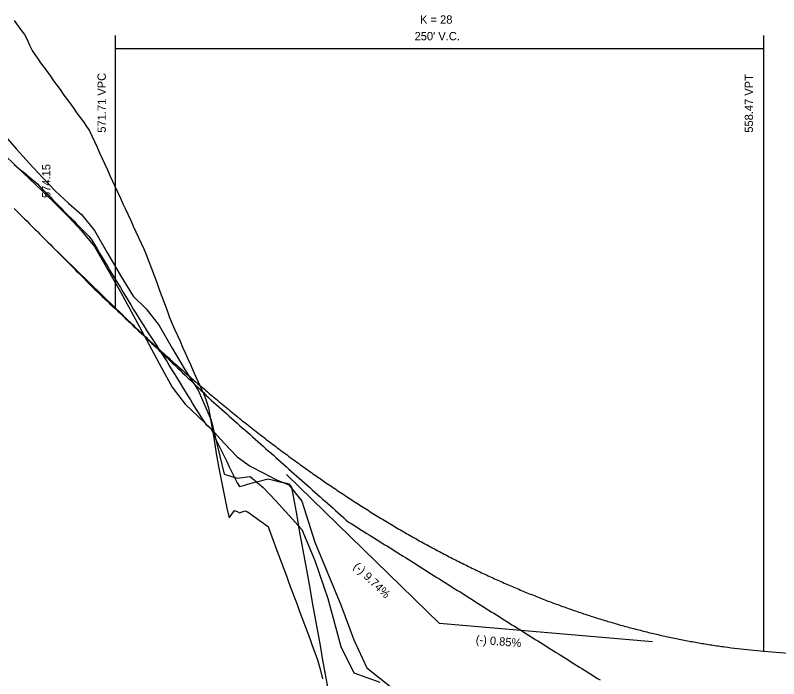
# Model space of a CAD drawing. Extents: x 1733571 to 1737171, y 1214895 to 1219895.
# Drawn here: x 1735066.5 to 1735360.8, y 1217969.6 to 1218225.5 of the extents above; entities that cross this region are included whole.
import ezdxf

# ---------------------------------------------------------------- set-up
doc = ezdxf.new("R2010")
doc.units = 0
for name, color, linetype in [('RD_DDB_GradeTX', 7, 'Continuous'), ('RD_DDB_Profile_EX', 7, 'Continuous'), ('RD_DDB_Profile_Lbl', 7, 'Continuous'), ('RD_DDB_Profile_PR', 7, 'Continuous'), ('RD_DDB_StripGrade', 7, 'Continuous'), ('RD_DDB_VCLbl', 7, 'Continuous'), ('RD_Sketch1', 7, 'Continuous'), ('RD_Sketch2', 7, 'Continuous'), ('RD_Sketch3', 7, 'Continuous'), ('RD_Sketch4', 7, 'Continuous')]:
    doc.layers.add(name, color=color, linetype=linetype)

msp = doc.modelspace()

# ---------------------------------------------------------------- linework, layer by layer
at = {"layer": 'RD_DDB_GradeTX'}
for p in [(1735170.98916, 1218048.35397), (1735312.11324, 1217983.88056)]:
    msp.add_line(p, (1735230.0087, 1217990.8522), dxfattribs=at)
at = {"layer": 'RD_DDB_Profile_EX'}
for points in [[(1735065.9887, 1218150.99954), (1735066.9887, 1218150.00594), (1735067.9887, 1218149.01167), (1735068.9887, 1218148.01672), (1735069.9887, 1218147.0211), (1735070.9887, 1218146.02371), (1735071.9887, 1218145.02278), (1735072.9887, 1218144.0251), (1735073.9887, 1218143.02676), (1735074.9887, 1218142.02777), (1735075.9887, 1218141.02812), (1735076.9887, 1218140.02782), (1735077.9887, 1218139.02687), (1735078.9887, 1218138.02527), (1735079.9887, 1218137.02301), (1735080.9887, 1218136.02011), (1735081.9887, 1218135.01656), (1735082.9887, 1218134.01237), (1735083.9887, 1218133.00752), (1735084.9887, 1218132.00204), (1735085.9887, 1218130.99591), (1735086.9887, 1218129.98914), (1735087.9887, 1218128.98172), (1735088.9887, 1218127.97367), (1735089.9887, 1218126.96498), (1735090.9887, 1218125.95565), (1735091.9887, 1218124.94569), (1735092.9887, 1218123.93509), (1735093.9887, 1218122.92385), (1735094.9887, 1218121.91198), (1735095.9887, 1218120.89935), (1735096.9887, 1218119.89679), (1735097.9887, 1218118.94243), (1735098.9887, 1218118.00112), (1735099.9887, 1218117.05932), (1735100.9887, 1218116.11703), (1735101.9887, 1218115.17425), (1735102.9887, 1218114.23098), (1735103.9887, 1218113.28722)], [(1735103.9887, 1218113.28722), (1735104.9887, 1218112.34298), (1735105.9887, 1218111.39825), (1735106.9887, 1218110.45303), (1735107.9887, 1218109.50733), (1735108.9887, 1218108.56115), (1735109.9887, 1218107.61448), (1735110.9887, 1218106.66733), (1735111.9887, 1218105.71971), (1735112.9887, 1218104.7716), (1735113.9887, 1218103.82302), (1735114.9887, 1218102.87396), (1735115.9887, 1218101.92443), (1735116.9887, 1218100.97442), (1735117.9887, 1218100.02393), (1735118.9887, 1218099.07298), (1735119.9887, 1218098.12155), (1735120.9887, 1218097.16965), (1735121.9887, 1218096.21729), (1735122.9887, 1218095.26445), (1735123.9887, 1218094.31115), (1735124.9887, 1218093.35738), (1735125.9887, 1218092.40315), (1735126.9887, 1218091.44845), (1735127.9887, 1218090.49329), (1735128.9887, 1218089.53767), (1735129.9887, 1218088.58158), (1735130.9887, 1218087.62504), (1735131.9887, 1218086.66804), (1735132.9887, 1218085.71058), (1735133.9887, 1218084.75266), (1735134.9887, 1218083.79429), (1735135.9887, 1218082.83547), (1735136.9887, 1218081.87619), (1735137.9887, 1218080.91646), (1735138.9887, 1218079.95627), (1735139.9887, 1218078.99564), (1735140.9887, 1218078.03456), (1735141.9887, 1218077.08082), (1735142.9887, 1218076.19411), (1735143.9887, 1218075.30671), (1735144.9887, 1218074.41916), (1735145.9887, 1218073.53161), (1735146.9887, 1218072.64407), (1735147.9887, 1218071.75652), (1735148.9887, 1218070.86898), (1735149.9887, 1218069.98143), (1735150.9887, 1218069.09389), (1735151.9887, 1218068.20634), (1735152.9887, 1218067.31879), (1735153.9887, 1218066.43125), (1735154.9887, 1218065.5437), (1735155.9887, 1218064.65616), (1735156.9887, 1218063.76861), (1735157.9887, 1218062.88106), (1735158.9887, 1218061.99352), (1735159.9887, 1218061.10597), (1735160.9887, 1218060.21843), (1735161.9887, 1218059.33088), (1735162.9887, 1218058.44334), (1735163.9887, 1218057.55579), (1735164.9887, 1218056.66824), (1735165.9887, 1218055.7807), (1735166.9887, 1218054.89315), (1735167.9887, 1218054.00561), (1735168.9887, 1218053.11806), (1735169.9887, 1218052.23052), (1735170.9887, 1218051.34297), (1735171.9887, 1218050.45543), (1735172.9887, 1218049.56788), (1735173.9887, 1218048.68033), (1735174.9887, 1218047.79279), (1735175.9887, 1218046.90524), (1735176.9887, 1218046.0177), (1735177.9887, 1218045.13015), (1735178.9887, 1218044.2426), (1735179.9887, 1218043.35506), (1735180.9887, 1218042.46751), (1735181.9887, 1218041.57997), (1735182.9887, 1218040.69242), (1735183.9887, 1218039.80488), (1735184.9887, 1218038.91733), (1735185.9887, 1218038.02978), (1735186.9887, 1218037.14224), (1735187.9887, 1218036.25469), (1735188.9887, 1218035.36715), (1735189.9887, 1218034.4796), (1735190.9887, 1218033.59205), (1735191.9887, 1218032.70451), (1735192.9887, 1218031.81697), (1735193.9887, 1218030.92942), (1735194.9887, 1218030.05114), (1735195.9887, 1218029.42658), (1735196.9887, 1218028.80201), (1735197.9887, 1218028.17744), (1735198.9887, 1218027.55288), (1735199.9887, 1218026.92831), (1735200.9887, 1218026.30374), (1735201.9887, 1218025.67918), (1735202.9887, 1218025.05461), (1735203.9887, 1218024.43004)], [(1735203.9887, 1218024.43004), (1735204.9887, 1218023.80548), (1735205.9887, 1218023.18091), (1735206.9887, 1218022.55634), (1735207.9887, 1218021.93178), (1735208.9887, 1218021.30721), (1735209.9887, 1218020.68264), (1735210.9887, 1218020.05808), (1735211.9887, 1218019.43351), (1735212.9887, 1218018.80894), (1735213.9887, 1218018.18438), (1735214.9887, 1218017.55981), (1735215.9887, 1218016.93524), (1735216.9887, 1218016.31068), (1735217.9887, 1218015.68611), (1735218.9887, 1218015.06154), (1735219.9887, 1218014.43443), (1735220.9887, 1218013.77698), (1735221.9887, 1218013.11783), (1735222.9887, 1218012.48577), (1735223.9887, 1218011.85765), (1735224.9887, 1218011.22952), (1735225.9887, 1218010.60139), (1735226.9887, 1218009.97327), (1735227.9887, 1218009.34514), (1735228.9887, 1218008.71702), (1735229.9887, 1218008.08889), (1735230.9887, 1218007.46076), (1735231.9887, 1218006.83264), (1735232.9887, 1218006.20451), (1735233.9887, 1218005.57638), (1735234.9887, 1218004.94826), (1735235.9887, 1218004.32013), (1735236.9887, 1218003.692), (1735237.9887, 1218003.06388), (1735238.9887, 1218002.43575), (1735239.9887, 1218001.80763), (1735240.9887, 1218001.1795), (1735241.9887, 1218000.55137), (1735242.9887, 1217999.92325), (1735243.9887, 1217999.29512), (1735244.9887, 1217998.66305), (1735245.9887, 1217998.00468), (1735246.9887, 1217997.35876), (1735247.9887, 1217996.73121), (1735248.9887, 1217996.10367), (1735249.9887, 1217995.47612), (1735250.9887, 1217994.84858), (1735251.9887, 1217994.22103), (1735252.9887, 1217993.59349), (1735253.9887, 1217992.96594), (1735254.9887, 1217992.3384), (1735255.9887, 1217991.71085), (1735256.9887, 1217991.08331), (1735257.9887, 1217990.45576), (1735258.9887, 1217989.82822), (1735259.9887, 1217989.20067), (1735260.9887, 1217988.57313), (1735261.9887, 1217987.94558), (1735262.9887, 1217987.31804), (1735263.9887, 1217986.6905), (1735264.9887, 1217986.06295), (1735265.9887, 1217985.43541), (1735266.9887, 1217984.80786), (1735267.9887, 1217984.18032), (1735268.9887, 1217983.55277), (1735269.9887, 1217982.92523), (1735270.9887, 1217982.29768), (1735271.9887, 1217981.67014), (1735272.9887, 1217981.04259), (1735273.9887, 1217980.41505), (1735274.9887, 1217979.7875), (1735275.9887, 1217979.15996), (1735276.9887, 1217978.53241), (1735277.9887, 1217977.90487), (1735278.9887, 1217977.27732), (1735279.9887, 1217976.64978), (1735280.9887, 1217976.02223), (1735281.9887, 1217975.39469), (1735282.9887, 1217974.76714), (1735283.9887, 1217974.1396), (1735284.9887, 1217973.51205), (1735285.9887, 1217972.88451), (1735286.9887, 1217972.25697), (1735287.9887, 1217971.62942), (1735288.9887, 1217971.00188), (1735289.9887, 1217970.37433), (1735290.9887, 1217969.74464), (1735291.9887, 1217969.19636)]]:
    msp.add_lwpolyline(points, dxfattribs=at)
at = {"layer": 'RD_DDB_Profile_PR'}
for p, q in [((1735080.0087, 1218136.99474), (1735105.0087, 1218112.63765)), ((1735355.0087, 1217980.23823), (1735459.5087, 1217971.36496))]:
    msp.add_line(p, q, dxfattribs=at)
msp.add_spline([(1735105.0087, 1218112.63765), (1735110.0087, 1218107.8107), (1735115.0087, 1218103.07269), (1735120.0087, 1218098.42361), (1735125.0087, 1218093.86348), (1735130.0087, 1218089.39227), (1735135.0087, 1218085.01001), (1735140.0087, 1218080.71669), (1735145.0087, 1218076.5123), (1735150.0087, 1218072.39684), (1735155.0087, 1218068.37033), (1735160.0087, 1218064.43275), (1735165.0087, 1218060.58411), (1735170.0087, 1218056.82441), (1735175.0087, 1218053.15364), (1735180.0087, 1218049.57182), (1735185.0087, 1218046.07892), (1735190.0087, 1218042.67497), (1735195.0087, 1218039.35995), (1735200.0087, 1218036.13387), (1735205.0087, 1218032.99673), (1735210.0087, 1218029.94852), (1735215.0087, 1218026.98926), (1735220.0087, 1218024.11892), (1735225.0087, 1218021.33753), (1735230.0087, 1218018.64507), (1735235.0087, 1218016.04155), (1735240.0087, 1218013.52697), (1735245.0087, 1218011.10133), (1735250.0087, 1218008.76462), (1735255.0087, 1218006.51685), (1735260.0087, 1218004.35801), (1735265.0087, 1218002.28812), (1735270.0087, 1218000.30716), (1735275.0087, 1217998.41513), (1735280.0087, 1217996.61205), (1735285.0087, 1217994.8979), (1735290.0087, 1217993.27269), (1735295.0087, 1217991.73642), (1735300.0087, 1217990.28908), (1735305.0087, 1217988.93068), (1735310.0087, 1217987.66122), (1735315.0087, 1217986.48069), (1735320.0087, 1217985.38911), (1735325.0087, 1217984.38646), (1735330.0087, 1217983.47274), (1735335.0087, 1217982.64797), (1735340.0087, 1217981.91213), (1735345.0087, 1217981.26523), (1735350.0087, 1217980.70726), (1735355.0087, 1217980.23823)], degree=3, dxfattribs=at)
at = {"layer": 'RD_DDB_VCLbl'}
for p, q in [((1735105.0087, 1218217.63765), (1735105.0087, 1218112.63765)), ((1735355.0087, 1218217.63765), (1735355.0087, 1217980.23823)), ((1735105.0087, 1218212.63765), (1735355.0087, 1218212.63765))]:
    msp.add_line(p, q, dxfattribs=at)
at = {"layer": 'RD_Sketch1'}
for points in [[(1735065.9887, 1218223.49498), (1735066.9887, 1218222.12595), (1735067.9887, 1218220.75747), (1735068.9887, 1218219.38955), (1735069.9887, 1218218.0222), (1735070.9887, 1218216.0499), (1735071.9887, 1218213.98873), (1735072.9887, 1218211.92795), (1735073.9887, 1218210.30375), (1735074.9887, 1218208.91654), (1735075.9887, 1218207.52936), (1735076.9887, 1218206.1422), (1735077.9887, 1218204.75506), (1735078.9887, 1218203.36794), (1735079.9887, 1218201.98086), (1735080.9887, 1218200.5938), (1735081.9887, 1218199.20677), (1735082.9887, 1218197.81977), (1735083.9887, 1218196.43281), (1735084.9887, 1218195.04588), (1735085.9887, 1218193.65898), (1735086.9887, 1218192.27213), (1735087.9887, 1218190.88531), (1735088.9887, 1218189.49853), (1735089.9887, 1218188.11179), (1735090.9887, 1218186.7251), (1735091.9887, 1218185.33846), (1735092.9887, 1218183.95186), (1735093.9887, 1218182.5653), (1735094.9887, 1218181.14545), (1735095.9887, 1218178.9647), (1735096.9887, 1218176.78409), (1735097.9887, 1218174.60362), (1735098.9887, 1218172.42329), (1735099.9887, 1218170.2431), (1735100.9887, 1218168.06306), (1735101.9887, 1218165.88317), (1735102.9887, 1218163.70343), (1735103.9887, 1218161.52384), (1735104.9887, 1218159.34441), (1735105.9887, 1218157.16514)], [(1735105.9887, 1218157.16514), (1735106.9887, 1218154.98603), (1735107.9887, 1218152.80708), (1735108.9887, 1218150.62829), (1735109.9887, 1218148.44967), (1735110.9887, 1218146.27123), (1735111.9887, 1218144.09295), (1735112.9887, 1218141.91486), (1735113.9887, 1218139.73693), (1735114.9887, 1218137.55919), (1735115.9887, 1218135.38163), (1735116.9887, 1218133.16911), (1735117.9887, 1218130.47648), (1735118.9887, 1218127.78387), (1735119.9887, 1218125.09126), (1735120.9887, 1218122.39866), (1735121.9887, 1218119.70608), (1735122.9887, 1218117.01352), (1735123.9887, 1218114.32097), (1735124.9887, 1218111.62845), (1735125.9887, 1218108.93596), (1735126.9887, 1218106.43146), (1735127.9887, 1218104.19693), (1735128.9887, 1218101.96195), (1735129.9887, 1218099.72653), (1735130.9887, 1218097.49065), (1735131.9887, 1218095.25433), (1735132.9887, 1218093.01757), (1735133.9887, 1218090.78037), (1735134.9887, 1218088.54274), (1735135.9887, 1218086.30467), (1735136.9887, 1218084.06617), (1735137.9887, 1218081.82724), (1735138.9887, 1218079.58788), (1735139.9887, 1218077.3481), (1735140.9887, 1218074.14211), (1735141.9887, 1218068.2958), (1735142.9887, 1218062.44968), (1735143.9887, 1218056.52864), (1735144.9887, 1218050.75292), (1735145.9887, 1218045.61322), (1735146.9887, 1218040.47351), (1735147.9887, 1218035.33381), (1735148.9887, 1218031.64265), (1735149.9887, 1218033.04646), (1735150.9887, 1218034.45027), (1735151.9887, 1218034.16846), (1735152.9887, 1218033.65102), (1735153.9887, 1218034.02593), (1735154.9887, 1218034.40083), (1735155.9887, 1218034.02248), (1735156.9887, 1218033.30345), (1735157.9887, 1218032.58443), (1735158.9887, 1218031.8654), (1735159.9887, 1218031.14637), (1735160.9887, 1218030.42735), (1735161.9887, 1218029.70832), (1735162.9887, 1218028.9893), (1735163.9887, 1218028.2774), (1735164.9887, 1218025.40591), (1735165.9887, 1218022.72297), (1735166.9887, 1218020.04003), (1735167.9887, 1218017.35709), (1735168.9887, 1218014.67416), (1735169.9887, 1218011.99122), (1735170.9887, 1218009.30828), (1735171.9887, 1218006.62534), (1735172.9887, 1218003.9424), (1735173.9887, 1218001.25947), (1735174.9887, 1217998.57653), (1735175.9887, 1217995.89359), (1735176.9887, 1217993.21065), (1735177.9887, 1217990.52771), (1735178.9887, 1217987.84477), (1735179.9887, 1217985.16184), (1735180.9887, 1217982.4789), (1735181.9887, 1217979.79596), (1735182.9887, 1217976.94359), (1735183.9887, 1217973.24941), (1735184.9887, 1217969.55522)]]:
    msp.add_lwpolyline(points, dxfattribs=at)
at = {"layer": 'RD_Sketch2'}
for points in [[(1735065.9887, 1218167.94041), (1735066.9887, 1218167.11329), (1735067.9887, 1218166.28762), (1735068.9887, 1218165.46338), (1735069.9887, 1218164.64059), (1735070.9887, 1218163.81923), (1735071.9887, 1218162.99932), (1735072.9887, 1218162.18085), (1735073.9887, 1218161.36383), (1735074.9887, 1218160.4029), (1735075.9887, 1218159.37707), (1735076.9887, 1218158.35252), (1735077.9887, 1218157.32926), (1735078.9887, 1218156.30729), (1735079.9887, 1218155.28661), (1735080.9887, 1218154.26723), (1735081.9887, 1218153.24913), (1735082.9887, 1218152.23234), (1735083.9887, 1218151.21683), (1735084.9887, 1218150.20263), (1735085.9887, 1218149.18972), (1735086.9887, 1218148.17811), (1735087.9887, 1218147.1678), (1735088.9887, 1218146.15879), (1735089.9887, 1218145.15109), (1735090.9887, 1218144.14468), (1735091.9887, 1218143.13958), (1735092.9887, 1218142.13579), (1735093.9887, 1218141.13331), (1735094.9887, 1218140.13213), (1735095.9887, 1218138.71683), (1735096.9887, 1218137.04748), (1735097.9887, 1218135.37953), (1735098.9887, 1218133.71297), (1735099.9887, 1218132.04782)], [(1735099.9887, 1218132.04782), (1735100.9887, 1218130.38407), (1735101.9887, 1218128.72172), (1735102.9887, 1218127.06078), (1735103.9887, 1218125.40124), (1735104.9887, 1218123.74312), (1735105.9887, 1218122.0864), (1735106.9887, 1218120.4311), (1735107.9887, 1218118.77722), (1735108.9887, 1218117.12475), (1735109.9887, 1218115.4737), (1735110.9887, 1218113.82407), (1735111.9887, 1218112.17586), (1735112.9887, 1218110.52908), (1735113.9887, 1218108.88372), (1735114.9887, 1218107.2887), (1735115.9887, 1218105.73979), (1735116.9887, 1218104.19223), (1735117.9887, 1218102.64601), (1735118.9887, 1218101.10115), (1735119.9887, 1218099.55763), (1735120.9887, 1218098.01546), (1735121.9887, 1218096.47464), (1735122.9887, 1218094.93518), (1735123.9887, 1218093.39708), (1735124.9887, 1218091.79007), (1735125.9887, 1218090.15472), (1735126.9887, 1218088.52068), (1735127.9887, 1218086.88793), (1735128.9887, 1218085.25649), (1735129.9887, 1218083.62636), (1735130.9887, 1218081.99753), (1735131.9887, 1218080.37001), (1735132.9887, 1218078.74379), (1735133.9887, 1218077.11889), (1735134.9887, 1218075.49531), (1735135.9887, 1218073.87304), (1735136.9887, 1218072.25209), (1735137.9887, 1218070.63245), (1735138.9887, 1218069.01414), (1735139.9887, 1218067.72846), (1735140.9887, 1218066.81852), (1735141.9887, 1218065.86923), (1735142.9887, 1218063.73841), (1735143.9887, 1218061.63385), (1735144.9887, 1218059.56893), (1735145.9887, 1218057.504), (1735146.9887, 1218055.43907), (1735147.9887, 1218053.37415), (1735148.9887, 1218051.30922), (1735149.9887, 1218049.2443), (1735150.9887, 1218047.17937), (1735151.9887, 1218045.11445), (1735152.9887, 1218043.77357), (1735153.9887, 1218044.04291), (1735154.9887, 1218044.31226), (1735155.9887, 1218044.5816), (1735156.9887, 1218044.85095), (1735157.9887, 1218045.12029), (1735158.9887, 1218045.38964), (1735159.9887, 1218045.65898), (1735160.9887, 1218045.92833), (1735161.9887, 1218046.19767), (1735162.9887, 1218046.46701), (1735163.9887, 1218046.64342), (1735164.9887, 1218046.4099), (1735165.9887, 1218046.17639), (1735166.9887, 1218045.94287), (1735167.9887, 1218045.70935), (1735168.9887, 1218045.47584), (1735169.9887, 1218045.24232), (1735170.9887, 1218045.0088), (1735171.9887, 1218044.77529), (1735172.9887, 1218043.49531), (1735173.9887, 1218037.93882), (1735174.9887, 1218032.38234), (1735175.9887, 1218026.82585), (1735176.9887, 1218021.26937), (1735177.9887, 1218015.71288), (1735178.9887, 1218010.1564), (1735179.9887, 1218004.59991), (1735180.9887, 1217999.04343), (1735181.9887, 1217993.48694), (1735182.9887, 1217987.93046), (1735183.9887, 1217982.37397), (1735184.9887, 1217976.81749), (1735185.9887, 1217971.261), (1735186.9887, 1217965.70452)]]:
    msp.add_lwpolyline(points, dxfattribs=at)
at = {"layer": 'RD_Sketch3'}
msp.add_lwpolyline([(1735061.9887, 1218179.64244), (1735066.9887, 1218173.85428), (1735071.9887, 1218168.26168), (1735076.9887, 1218162.86481), (1735081.9887, 1218157.66381), (1735086.9887, 1218152.98871), (1735091.9887, 1218148.64942), (1735096.9887, 1218142.43266), (1735101.9887, 1218133.67435), (1735106.9887, 1218125.10498), (1735111.9887, 1218117.12762), (1735116.9887, 1218112.29488), (1735121.9887, 1218105.81067), (1735126.9887, 1218097.15164), (1735131.9887, 1218088.63353), (1735136.9887, 1218080.94189), (1735141.9887, 1218069.34699), (1735146.9887, 1218048.44715), (1735151.9887, 1218047.00976), (1735156.9887, 1218047.59568), (1735161.9887, 1218043.3918), (1735166.9887, 1218038.2704), (1735171.9887, 1218032.73707), (1735176.9887, 1218027.20373), (1735181.9887, 1218015.19915), (1735186.9887, 1218000.51172), (1735191.9887, 1217982.04078), (1735196.9887, 1217971.86993), (1735201.9887, 1217970.09506), (1735206.9887, 1217968.32019)], dxfattribs=at)
at = {"layer": 'RD_Sketch4'}
msp.add_lwpolyline([(1735061.9887, 1218172.02756), (1735066.9887, 1218167.1477), (1735071.9887, 1218162.35388), (1735076.9887, 1218157.62436), (1735081.9887, 1218152.78556), (1735086.9887, 1218147.74395), (1735091.9887, 1218142.29511), (1735096.9887, 1218136.34178), (1735101.9887, 1218127.604), (1735106.9887, 1218118.74914), (1735111.9887, 1218109.75255), (1735116.9887, 1218100.52584), (1735121.9887, 1218091.18779), (1735126.9887, 1218082.00387), (1735131.9887, 1218075.5258), (1735136.9887, 1218070.74973), (1735141.9887, 1218066.02028), (1735146.9887, 1218060.51569), (1735151.9887, 1218055.2416), (1735156.9887, 1218051.59983), (1735161.9887, 1218049.05129), (1735166.9887, 1218046.50276), (1735171.9887, 1218044.35436), (1735176.9887, 1218038.13694), (1735181.9887, 1218022.24923), (1735186.9887, 1218010.20371), (1735191.9887, 1217998.15819), (1735196.9887, 1217984.62556), (1735201.9887, 1217973.88029), (1735206.9887, 1217969.86147), (1735211.9887, 1217965.84265)], dxfattribs=at)

# ---------------------------------------------------------------- texts
at = {"layer": 'RD_DDB_GradeTX'}
for s, rotation, p in [('(-) 9.74%', 315.746276, (1735196.59942, 1218012.60941)), ('(-) 0.85%', 355.1465568, (1735243.93022, 1217983.23655))]:
    msp.add_text(s, height=3.2, rotation=rotation, dxfattribs=at).set_placement(p)
at = {"layer": 'RD_DDB_Profile_Lbl'}
msp.add_text('574.15', height=3.2, rotation=90, dxfattribs=at).set_placement((1735080.0087, 1218154.99474))
at = {"layer": 'RD_DDB_StripGrade'}
for s, p in [('571.71 VPC', (1735101.37857, 1218180.1727)), ('558.47 VPT', (1735350.93193, 1218180.1727))]:
    msp.add_text(s, height=3.2, rotation=90, dxfattribs=at).set_placement(p)
at = {"layer": 'RD_DDB_VCLbl'}
for s, p in [('K = 28', (1735222.52987, 1218222.20886)), ("250' V.C.", (1735220.444, 1218215.80886))]:
    msp.add_text(s, height=3.2, dxfattribs=at).set_placement(p)

doc.saveas('drawing.dxf')
